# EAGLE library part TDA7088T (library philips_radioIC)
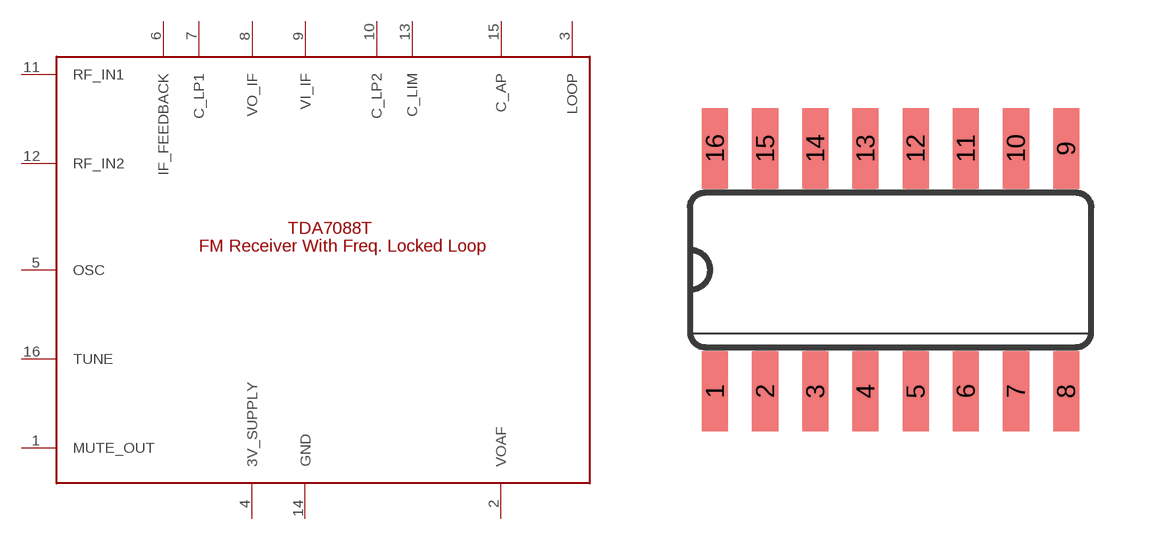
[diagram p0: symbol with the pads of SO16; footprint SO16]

Designator prefix -

## TDA7088T  [SO16]
1  MUTE_OUT
2  VOAF
3  LOOP
4  3V_SUPPLY
5  OSC
6  IF_FEEDBACK
7  C_LP1
8  VO_IF
9  VI_IF
10  C_LP2
11  RF_IN1
12  RF_IN2
13  C_LIM
14  GND
15  C_AP
16  TUNE

## Footprint SO16 (pad centres in mm)
Small Outline Package 16
smd 0.66 x 2.032: 1 -4.445,-3.073; 2 -3.175,-3.073; 3 -1.905,-3.073; 4 -0.635,-3.073; 5 0.635,-3.073; 6 1.905,-3.073; 7 3.175,-3.073; 8 4.445,-3.073; 9 4.445,3.073; 10 3.175,3.073; 11 1.905,3.073; 12 0.635,3.073; 13 -0.635,3.073; 14 -1.905,3.073; 15 -3.175,3.073; 16 -4.445,3.073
